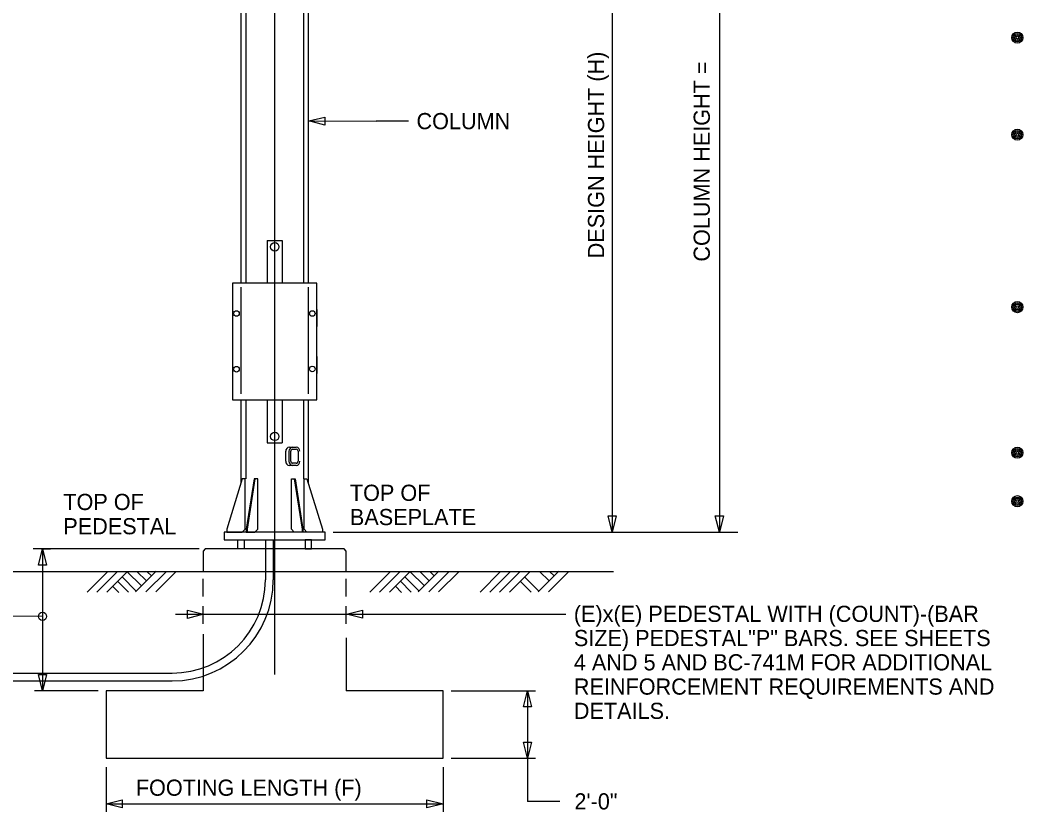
# Model space of a CAD drawing. Extents: x 3829340 to 3831660, y 499389 to 501171.
# Drawn here: x 3829781.8 to 3829967.8, y 499657.2 to 499804 of the extents above; entities that cross this region are included whole.
import ezdxf

# ---------------------------------------------------------------- set-up
doc = ezdxf.new("R2010")
doc.units = 0
for name, color, linetype in [('0-ANCHOR', 7, 'Continuous'), ('0-DEVICE ATTACH', 7, 'Continuous'), ('CNTR', 7, 'Continuous'), ('Default', 7, 'Continuous'), ('DIM TXT', 7, 'Continuous'), ('foundation', 7, 'Continuous'), ('grade', 7, 'Continuous'), ('structure', 7, 'Continuous')]:
    doc.layers.add(name, color=color, linetype=linetype)

msp = doc.modelspace()

# ---------------------------------------------------------------- linework, layer by layer
at = {"layer": '0-ANCHOR'}
for points in [[(3829822.17, 499707.66), (3829823.34, 499707.66), (3829823.34, 499705.97), (3829822.17, 499705.97)], [(3829835.84, 499707.66), (3829834.67, 499707.66), (3829834.67, 499705.97), (3829835.84, 499705.97)]]:
    msp.add_lwpolyline(points, close=True, dxfattribs=at)
at = {"layer": '0-DEVICE ATTACH'}
msp.add_lwpolyline([(3829830.44, 499733.61), (3829836.82, 499733.61), (3829836.82, 499755.23), (3829821.2, 499755.23), (3829821.2, 499733.61), (3829830.44, 499733.61)], dxfattribs=at)
at = {"layer": 'CNTR'}
msp.add_line((3829829.01, 499937.06), (3829829.01, 499682.67), dxfattribs=at)
at = {"layer": 'Default'}
for p, q in [((3829825.36, 499718.99), (3829823.91, 499709.62)), ((3829832.65, 499718.99), (3829834.1, 499709.62)), ((3829823.91, 499709.62), (3829823.91, 499709.1)), ((3829834.1, 499709.62), (3829834.1, 499709.1))]:
    msp.add_line(p, q, dxfattribs=at)
at = {"layer": 'DIM TXT'}
for p, q in [((3829891.62, 499859.09), (3829891.62, 499709.1)), ((3829911.49, 499854.37), (3829911.49, 499709.1)), ((3829835.33, 499785.33), (3829847.82, 499785.31)), ((3829853.82, 499785.31), (3829847.82, 499785.31)), ((3829839.88, 499709.1), (3829914.89, 499709.1)), ((3829815.04, 499705.97), (3829784.26, 499705.97)), ((3829785.76, 499705.97), (3829787.47, 499705.97)), ((3829785.97, 499705.97), (3829785.97, 499679.66)), ((3829785.97, 499693.46), (3829780.14, 499693.48)), ((3829810.63, 499693.84), (3829883, 499693.84)), ((3829796.26, 499679.66), (3829784.47, 499679.66)), ((3829861.76, 499679.66), (3829877.41, 499679.66)), ((3829875.91, 499679.66), (3829875.91, 499667.16)), ((3829875.91, 499673.41), (3829875.88, 499659.15)), ((3829861.76, 499667.16), (3829877.41, 499667.16)), ((3829797.76, 499665.49), (3829797.76, 499657.19)), ((3829860.26, 499665.49), (3829860.26, 499657.19)), ((3829797.76, 499658.69), (3829860.26, 499658.69)), ((3829881.88, 499659.15), (3829875.88, 499659.15))]:
    msp.add_line(p, q, dxfattribs=at)
for points in [[(3829838.33, 499784.57), (3829835.33, 499785.33), (3829838.33, 499786.07)], [(3829892.37, 499712.1), (3829891.62, 499709.1), (3829890.87, 499712.1)], [(3829912.24, 499712.1), (3829911.49, 499709.1), (3829910.74, 499712.1)], [(3829785.22, 499702.97), (3829785.97, 499705.97), (3829786.72, 499702.97)], [(3829812.83, 499694.59), (3829815.83, 499693.84), (3829812.83, 499693.09)], [(3829845.32, 499693.12), (3829842.32, 499693.87), (3829845.32, 499694.62)], [(3829786.72, 499682.66), (3829785.97, 499679.66), (3829785.22, 499682.66)], [(3829875.16, 499676.66), (3829875.91, 499679.66), (3829876.66, 499676.66)], [(3829876.66, 499670.16), (3829875.91, 499667.16), (3829875.16, 499670.16)], [(3829800.76, 499657.94), (3829797.76, 499658.69), (3829800.76, 499659.44)], [(3829857.26, 499659.44), (3829860.26, 499658.69), (3829857.26, 499657.94)]]:
    msp.add_lwpolyline(points, close=True, dxfattribs=at)
for centre, radius in [((3829966.75, 499800.79), 1.04), ((3829966.75, 499800.79), 0.783), ((3829966.75, 499800.79), 0.522), ((3829966.75, 499800.79), 0.261), ((3829966.75, 499800.79), 0.00000209), ((3829966.75, 499782.79), 1.04), ((3829966.75, 499782.79), 0.783), ((3829966.75, 499782.79), 0.522), ((3829966.75, 499782.79), 0.261), ((3829966.75, 499782.79), 0.00000209), ((3829966.75, 499750.81), 1.04), ((3829966.75, 499750.81), 0.783), ((3829966.75, 499750.81), 0.522), ((3829966.75, 499750.81), 0.261), ((3829966.75, 499750.81), 0.00000209), ((3829966.75, 499723.81), 1.04), ((3829966.75, 499723.81), 0.783), ((3829966.75, 499723.81), 0.522), ((3829966.75, 499723.81), 0.261), ((3829966.75, 499723.81), 0.00000209), ((3829966.75, 499714.81), 1.04), ((3829966.75, 499714.81), 0.783), ((3829966.75, 499714.81), 0.522), ((3829966.75, 499714.81), 0.261), ((3829966.75, 499714.81), 0.00000209), ((3829785.96, 499693.46), 0.75)]:
    msp.add_circle(centre, radius, dxfattribs=at)
at = {"layer": 'foundation'}
for p, q in [((3829827.31, 499707.66), (3829827.31, 499700.24)), ((3829828.75, 499707.66), (3829828.75, 499700.24)), ((3829815.73, 499697.16), (3829815.73, 499700.44)), ((3829842.29, 499697.16), (3829842.29, 499700.44)), ((3829815.73, 499692.1), (3829815.73, 499695.38)), ((3829842.29, 499692.1), (3829842.29, 499695.38)), ((3829815.73, 499690.15), (3829815.73, 499679.66)), ((3829842.29, 499689.5), (3829842.29, 499679.66)), ((3829766.51, 499682.93), (3829810, 499682.93)), ((3829767.36, 499681.49), (3829810, 499681.49)), ((3829815.73, 499679.66), (3829797.76, 499679.66)), ((3829797.76, 499679.66), (3829797.76, 499667.16)), ((3829860.26, 499679.66), (3829842.29, 499679.66)), ((3829860.26, 499667.16), (3829860.26, 499679.66)), ((3829797.76, 499667.16), (3829860.26, 499667.16))]:
    msp.add_line(p, q, dxfattribs=at)
msp.add_lwpolyline([(3829842.29, 499701.78), (3829842.29, 499705.58), (3829841.9, 499705.97), (3829816.12, 499705.97), (3829815.73, 499705.58), (3829815.73, 499701.78)], dxfattribs=at)
for radius in [18.75, 17.31]:
    msp.add_arc((3829810, 499700.24), radius, 270, 0, dxfattribs=at)
at = {"layer": 'grade'}
for p, q in [((3829769.6, 499701.78), (3829891.88, 499701.78)), ((3829794.25, 499697.96), (3829798.06, 499701.78)), ((3829796.04, 499697.96), (3829799.86, 499701.81)), ((3829797.88, 499697.97), (3829801.71, 499701.81)), ((3829800.71, 499700.8), (3829803.36, 499698.16)), ((3829801.63, 499701.81), (3829804.34, 499699.11)), ((3829803.19, 499697.98), (3829807.04, 499701.84)), ((3829803.47, 499701.81), (3829805.24, 499700.05)), ((3829805.14, 499697.98), (3829808.93, 499701.78)), ((3829805.34, 499701.81), (3829806.18, 499700.98)), ((3829806.98, 499697.98), (3829810.77, 499701.78)), ((3829846.69, 499697.96), (3829850.5, 499701.78)), ((3829848.48, 499697.96), (3829852.31, 499701.81)), ((3829850.32, 499697.97), (3829854.15, 499701.81)), ((3829853.15, 499700.8), (3829855.8, 499698.16)), ((3829854.07, 499701.81), (3829856.78, 499699.11)), ((3829855.63, 499697.98), (3829859.48, 499701.84)), ((3829855.91, 499701.81), (3829857.68, 499700.05)), ((3829857.58, 499697.98), (3829861.37, 499701.78)), ((3829857.78, 499701.81), (3829858.62, 499700.98)), ((3829859.43, 499697.98), (3829863.21, 499701.78)), ((3829867.12, 499697.94), (3829870.93, 499701.76)), ((3829868.93, 499697.96), (3829872.73, 499701.78)), ((3829870.71, 499697.96), (3829874.54, 499701.81)), ((3829872.55, 499697.97), (3829876.38, 499701.81)), ((3829875.38, 499700.8), (3829878.03, 499698.16)), ((3829877.86, 499697.98), (3829881.71, 499701.84)), ((3829878.15, 499701.81), (3829879.91, 499700.05)), ((3829879.81, 499697.98), (3829883.6, 499701.78)), ((3829880.01, 499701.81), (3829880.85, 499700.98)), ((3829798.97, 499699.06), (3829800.12, 499697.91)), ((3829799.89, 499699.98), (3829801.9, 499697.97)), ((3829851.41, 499699.06), (3829852.56, 499697.91)), ((3829852.33, 499699.98), (3829854.34, 499697.97)), ((3829874.56, 499699.98), (3829876.57, 499697.97))]:
    msp.add_line(p, q, dxfattribs=at)
at = {"layer": 'structure'}
for p, q in [((3829834.36, 499883.83), (3829834.36, 499755.23)), ((3829835.26, 499883.83), (3829835.26, 499755.23)), ((3829822.76, 499834.61), (3829822.76, 499755.23)), ((3829822.76, 499834.61), (3829822.76, 499755.23)), ((3829823.66, 499834.61), (3829823.66, 499755.23)), ((3829827.62, 499763.17), (3829830.43, 499763.17)), ((3829827.62, 499763.17), (3829827.62, 499755.22)), ((3829830.43, 499763.17), (3829830.43, 499755.28)), ((3829822.76, 499754.52), (3829822.76, 499734.7)), ((3829835.26, 499754.52), (3829835.26, 499734.7)), ((3829821.2, 499750.35), (3829821.2, 499747.23)), ((3829836.82, 499750.35), (3829836.82, 499747.23)), ((3829821.2, 499741.66), (3829821.2, 499738.53)), ((3829836.82, 499741.66), (3829836.82, 499738.53)), ((3829822.76, 499733.61), (3829822.76, 499718.14)), ((3829822.76, 499733.61), (3829822.76, 499718.14)), ((3829823.66, 499733.61), (3829823.66, 499718.99)), ((3829827.62, 499733.61), (3829827.62, 499725.67)), ((3829830.43, 499733.62), (3829830.43, 499725.67)), ((3829834.36, 499733.61), (3829834.36, 499718.99)), ((3829835.26, 499733.61), (3829835.26, 499718.14)), ((3829827.62, 499725.67), (3829830.43, 499725.67)), ((3829831.74, 499724.85), (3829832.42, 499724.85)), ((3829832.35, 499724.85), (3829833.03, 499724.85)), ((3829832.35, 499724.46), (3829833.03, 499724.46)), ((3829831.06, 499722.25), (3829831.06, 499724.07)), ((3829831.68, 499722.25), (3829831.68, 499724.07)), ((3829832.02, 499722.25), (3829832.02, 499724.07)), ((3829833.37, 499724.07), (3829833.37, 499722.25)), ((3829832.42, 499721.47), (3829831.74, 499721.47)), ((3829833.03, 499721.86), (3829832.35, 499721.86)), ((3829833.03, 499721.47), (3829832.35, 499721.47)), ((3829823.02, 499718.99), (3829820.15, 499709.62)), ((3829823.54, 499709.62), (3829823.54, 499718.99)), ((3829825.2, 499718.99), (3829823.74, 499709.62)), ((3829825.36, 499718.99), (3829825.2, 499718.99)), ((3829825.88, 499718.99), (3829825.36, 499718.99)), ((3829825.88, 499709.62), (3829825.88, 499718.99)), ((3829832.13, 499709.62), (3829832.13, 499718.99)), ((3829832.13, 499718.99), (3829832.65, 499718.99)), ((3829832.65, 499718.99), (3829832.82, 499718.99)), ((3829832.82, 499718.99), (3829834.27, 499709.62)), ((3829834.48, 499709.62), (3829834.48, 499718.99)), ((3829835, 499718.99), (3829837.86, 499709.62)), ((3829823.02, 499709.09), (3829823.54, 499709.62)), ((3829823.74, 499709.62), (3829823.74, 499709.1)), ((3829825.37, 499709.1), (3829825.88, 499709.62)), ((3829832.65, 499709.1), (3829832.13, 499709.62)), ((3829834.27, 499709.62), (3829834.27, 499709.1)), ((3829835, 499709.09), (3829834.48, 499709.62)), ((3829820.15, 499709.1), (3829823.02, 499709.1)), ((3829823.74, 499709.1), (3829825.37, 499709.1)), ((3829834.27, 499709.1), (3829832.65, 499709.1)), ((3829837.86, 499709.1), (3829834.99, 499709.1))]:
    msp.add_line(p, q, dxfattribs=at)
for points in [[(3829823.54, 499718.99), (3829823.02, 499718.99)], [(3829834.48, 499718.99), (3829835, 499718.99)], [(3829820.15, 499709.62), (3829820.15, 499709.1)], [(3829837.86, 499709.62), (3829837.86, 499709.1)]]:
    msp.add_lwpolyline(points, dxfattribs=at)
msp.add_lwpolyline([(3829819.63, 499707.66), (3829838.38, 499707.66), (3829838.38, 499709.1), (3829819.63, 499709.1)], close=True, dxfattribs=at)
for centre, radius in [((3829829.03, 499762), 0.781), ((3829821.93, 499749.63), 0.521), ((3829836, 499749.63), 0.521), ((3829821.93, 499739.3), 0.521), ((3829836, 499739.34), 0.521), ((3829829.03, 499726.84), 0.781)]:
    msp.add_circle(centre, radius, dxfattribs=at)
for centre, major_axis, start_param, end_param in [((3829831.74, 499724.07), (0, -0.781), 3.141593, 4.712389), ((3829832.35, 499724.07), (0, -0.781), 3.141593, 4.712389), ((3829832.35, 499724.07), (0, -0.391), 3.141593, 4.712389), ((3829832.42, 499724.07), (0, 0.781), 6.28316, 6.283185), ((3829833.03, 499724.07), (0, 0.781), 4.712389, 6.283185), ((3829833.03, 499724.07), (0, 0.391), 4.712389, 6.283185), ((3829831.74, 499722.25), (0, -0.781), 4.712389, 6.283185), ((3829832.35, 499722.25), (0, -0.781), 4.712389, 6.283185), ((3829832.35, 499722.25), (0, -0.391), 4.712389, 6.283185), ((3829833.03, 499722.25), (0, -0.781), 0, 1.570796), ((3829833.03, 499722.25), (0, -0.391), 0, 1.570796)]:
    msp.add_ellipse(centre, major_axis=major_axis, ratio=0.866025, start_param=start_param, end_param=end_param, dxfattribs=at)

# ---------------------------------------------------------------- texts
at = {"layer": 'DIM TXT'}
for s, p in [('DESIGN HEIGHT (H)', (3829890.12, 499759.86)), ('COLUMN HEIGHT =', (3829909.72, 499759.25))]:
    msp.add_text(s, height=2.9999, rotation=90, dxfattribs=at).set_placement(p)
for s, height, p in [('COLUMN', 3, (3829855.32, 499783.81)), ('TOP OF ', 3, (3829842.97, 499714.88)), ('TOP OF ', 3, (3829789.82, 499713.18)), ('BASEPLATE', 3, (3829842.97, 499710.38)), ('PEDESTAL', 3, (3829789.82, 499708.68)), ('(E)x(E) PEDESTAL WITH (COUNT)-(BAR ', 2.9999, (3829884.5, 499692.43)), ('SIZE) PEDESTAL"P" BARS. SEE SHEETS ', 2.9999, (3829884.5, 499687.94)), ('4 AND 5 AND BC-741M FOR ADDITIONAL ', 2.9999, (3829884.5, 499683.44)), ('REINFORCEMENT REQUIREMENTS AND ', 2.9999, (3829884.5, 499678.94)), ('DETAILS.', 3, (3829884.5, 499674.44)), ('FOOTING LENGTH (F)', 2.9999, (3829803.27, 499660.19)), ('2\'-0"', 3, (3829884.61, 499657.65))]:
    msp.add_text(s, height=height, dxfattribs=at).set_placement(p)

doc.saveas('drawing.dxf')
